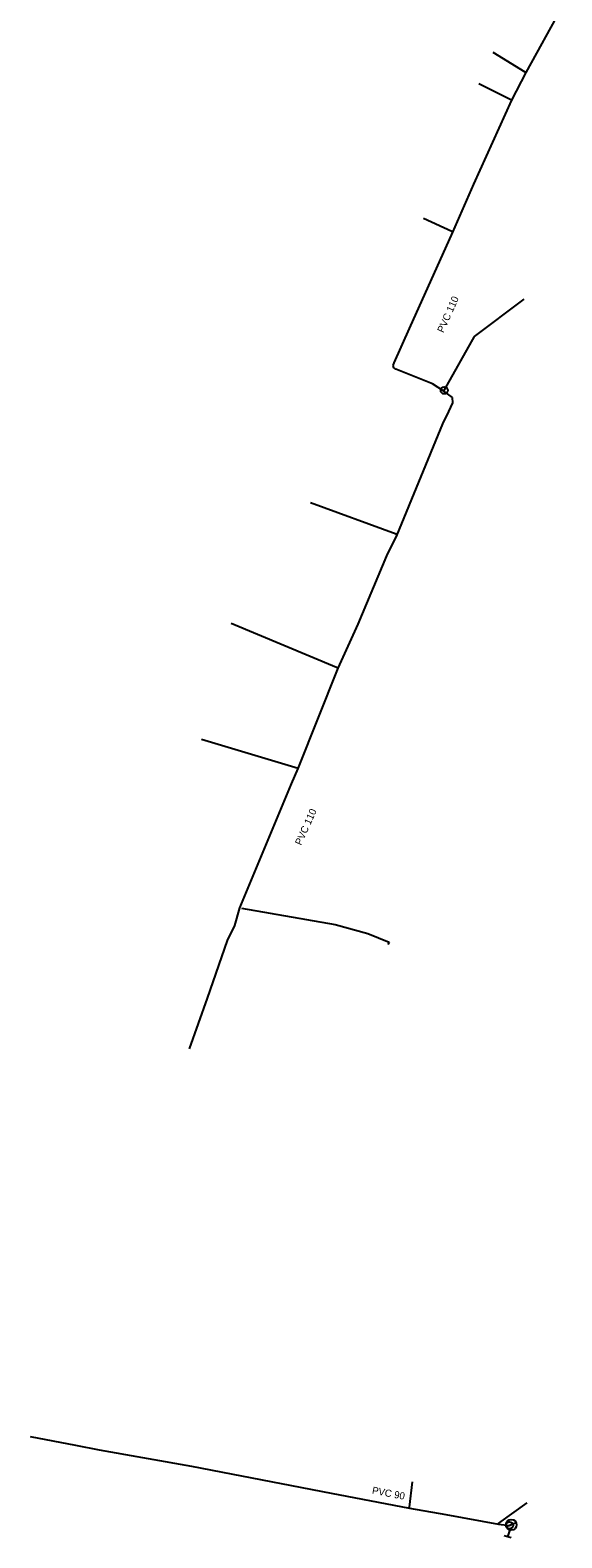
# Model space of a CAD drawing. Extents: x -643485 to -643037, y -1068047 to -1067198.
# Drawn here: x -643419.1 to -643345.1, y -1067832.6 to -1067622.7 of the extents above; entities that cross this region are included whole.
import ezdxf

# ---------------------------------------------------------------- set-up
doc = ezdxf.new("R2010")
doc.units = 0
doc.layers.add('Level 0', color=7, linetype='Continuous')

msp = doc.modelspace()

# ---------------------------------------------------------------- linework, layer by layer
at = {"layer": 'Level 0'}
for p, q in [((-643350, -1067628.62), (-643345.05, -1067619.61)), ((-643350.14, -1067628.54), (-643354.6, -1067625.81)), ((-643352.15, -1067632.39), (-643356.63, -1067630.19)), ((-643352, -1067632.47), (-643350, -1067628.62)), ((-643350, -1067628.62), (-643350.14, -1067628.54)), ((-643357.33, -1067644.14), (-643352, -1067632.47)), ((-643352, -1067632.47), (-643352.15, -1067632.39)), ((-643360.24, -1067650.83), (-643357.33, -1067644.14)), ((-643360.36, -1067650.75), (-643364.34, -1067648.91)), ((-643366.27, -1067664.26), (-643360.24, -1067650.83)), ((-643360.24, -1067650.83), (-643360.36, -1067650.75)), ((-643357.21, -1067665.36), (-643350.28, -1067660.16)), ((-643368.39, -1067669.02), (-643366.27, -1067664.26)), ((-643361.43, -1067672.86), (-643357.21, -1067665.36)), ((-643368.53, -1067669.4), (-643368.39, -1067669.02)), ((-643368.45, -1067669.71), (-643368.53, -1067669.4)), ((-643368.19, -1067669.89), (-643368.45, -1067669.71)), ((-643363.07, -1067671.96), (-643368.19, -1067669.89)), ((-643361.5, -1067672.95), (-643363.07, -1067671.96)), ((-643361.5, -1067672.95), (-643361.43, -1067672.86)), ((-643360.28, -1067673.86), (-643361.5, -1067672.95)), ((-643360.23, -1067674.58), (-643360.28, -1067673.86)), ((-643361.62, -1067677.52), (-643360.78, -1067675.78)), ((-643360.78, -1067675.78), (-643360.23, -1067674.58)), ((-643368.01, -1067692.99), (-643361.62, -1067677.52)), ((-643368.14, -1067692.89), (-643380.08, -1067688.51)), ((-643369.41, -1067695.9), (-643368.01, -1067692.99)), ((-643368.01, -1067692.99), (-643368.14, -1067692.89)), ((-643373.44, -1067705.41), (-643369.41, -1067695.9)), ((-643376.45, -1067711.44), (-643391.11, -1067705.29)), ((-643376.22, -1067711.54), (-643373.44, -1067705.41)), ((-643381.77, -1067725.52), (-643376.22, -1067711.54)), ((-643376.22, -1067711.54), (-643376.45, -1067711.44)), ((-643381.77, -1067725.52), (-643395.26, -1067721.46)), ((-643382.7, -1067727.62), (-643381.77, -1067725.52)), ((-643389.92, -1067744.9), (-643382.7, -1067727.62)), ((-643390.59, -1067747.35), (-643389.92, -1067744.9)), ((-643389.67, -1067744.94), (-643376.62, -1067747.21)), ((-643391.62, -1067749.46), (-643390.59, -1067747.35)), ((-643376.62, -1067747.21), (-643372.07, -1067748.47)), ((-643394.41, -1067757.45), (-643391.62, -1067749.46)), ((-643372.07, -1067748.47), (-643369.13, -1067749.66)), ((-643369.13, -1067749.66), (-643369.31, -1067750.01)), ((-643396.93, -1067764.54), (-643394.41, -1067757.45)), ((-643419.12, -1067818.49), (-643412.8, -1067819.69)), ((-643412.8, -1067819.69), (-643409.52, -1067820.35)), ((-643409.52, -1067820.35), (-643396.62, -1067822.6)), ((-643396.62, -1067822.6), (-643377.19, -1067826.38)), ((-643366.26, -1067828.31), (-643365.84, -1067824.79)), ((-643377.19, -1067826.38), (-643366.28, -1067828.47)), ((-643366.28, -1067828.47), (-643366.26, -1067828.31)), ((-643366.28, -1067828.47), (-643361.21, -1067829.35)), ((-643361.21, -1067829.35), (-643353.86, -1067830.7)), ((-643353.81, -1067830.54), (-643349.9, -1067827.74)), ((-643353.86, -1067830.7), (-643353.81, -1067830.54)), ((-643353.86, -1067830.7), (-643352.34, -1067830.86)), ((-643351.4, -1067830.5), (-643352.8, -1067831.06)), ((-643352.31, -1067831.5), (-643352.6, -1067832.46)), ((-643352.34, -1067830.86), (-643352.1, -1067830.78)), ((-643352.12, -1067832.6), (-643353.08, -1067832.31))]:
    msp.add_line(p, q, dxfattribs=at)
for centre, radius in [((-643361.43, -1067672.86), 0.5), ((-643352.1, -1067830.78), 0.75), ((-643352.34, -1067830.86), 0.5)]:
    msp.add_circle(centre, radius, dxfattribs=at)

# ---------------------------------------------------------------- texts
for s, rotation, p in [('PVC 110', 65.993, (-643361.55, -1067664.92)), ('PVC 110', 65.993, (-643381.36, -1067736.27)), ('PVC 90', 349.155, (-643371.55, -1067826.44))]:
    msp.add_text(s, height=1, rotation=rotation, dxfattribs=at).set_placement(p)

doc.saveas('drawing.dxf')
